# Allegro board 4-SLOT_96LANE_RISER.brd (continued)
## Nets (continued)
GND: C1.2(B) C2.2(B) C3.2(B) C4.2(B) C5.2(B) C6.2(B) C7.2(B) C8.2(B) C9.2(B) C10.2(B) C11.2(B) C12.2(B) C13.2(B) C14.2(B) C15.2(B) C16.2(B) C17.2(B) C18.2(B) C19.2(B) C20.2(B) C21.2(B) C22.2(B) C215.2(B) C216.2(B) C217.2(B) C218.2(B) C219.2(B) C220.2(B) C221.2(B) C222.2(B) C223.2(B) C224.2(B) C225.2(B) C226.2(B) C227.2(B) C228.2(B) C229.2(B) C230.2(B) C231.2(B) C232.2(B) C233.2(B) C234.2(B) C235.2(B) C236.2(B) C237.2(B) C238.2(B) C239.2(B) C240.2(B) C241.2(B) C242.2(B) C243.2(B) C244.2(B) C245.2(B) C246.2(B) C247.2(B) C248.2(B) C249.2(B) C250.2(B) C251.2(B) C252.2(B) C253.2(B) C254.2(B) C255.2(B) C256.2(B) C257.2(B) C258.2(B) C259.2(B) C261.2(B) C268.2(B) C269.2(B) C270.2(B) C271.2(B) C272.2(B) C273.2(B) C274.2(B) C275.2(B) C276.2(B) C277.2(B) C278.2(B) C279.2(B) C280.2(B) C281.2(B) C282.2(B) C283.2(B) C284.2(B) C285.2(B) C286.2(B) C287.2(B) C288.2(B) C289.2(B) C290.2(B) C291.2(B) C292.2(B) C293.2(B) C294.2(B) C295.2(B) C296.2(B) C297.2(B) C298.2(B) C299.2(B) C300.2(B) C301.2(B) C302.2(B) C303.2(B) C304.2(B) C305.2(B) C306.2(B) C307.2(B) C308.2(B) C309.2(B) C310.2(B) C311.2(B) C312.2(B) C313.2(B) C314.2(B) C315.2(B) C316.2(B) C317.2(B) C318.2(B) C319.2(B) C320.2(B) C321.2(B) C322.2(B) C323.2(B) C324.2(B) C325.2(B) C326.2(B) C327.2(B) C328.2(B) C329.2(B) C330.2(B) C331.2(B) C332.2(B) C333.2(B) C334.2(B) C335.2(B) C336.2(B) C337.2(B) C338.2(B) C339.2(B) C340.2(B) C341.2(B) C342.2(B) C343.2(B) C344.2(B) C345.2(B) C346.2(B) C347.2(B) C348.2(B) C349.2(B) C350.2(B) C351.2(B) C352.2(B) C353.2(B) C354.2(B) C355.2(B) C356.2(B) C357.2(B) C358.2(B) C359.2(B) C360.2(B) C361.2(B) C362.2(B) C363.2(B) C364.2(B) C365.2(B) C366.2(B) C367.2(B) C368.2(B) C369.2(B) C370.2(B) C371.2(B) C372.2(B) C373.2(B) C374.2(B) C375.2(B) C376.2(B) C377.2(B) C378.2(B) C379.2(B) C380.2(B) C381.2(B) C382.2(B) C383.2(B) C384.2(B) C385.2(B) C386.2(B) C387.2(B) C388.2(B) C389.2(B) C390.2(B) C391.2(B) C392.2(B) C393.2(B) C394.2(B) C395.2(B) C396.2(B) C397.2(B) C398.2(B) C399.2(B) C400.2(B) C401.2(B) C402.2(B) C403.2(B) C404.2(B) C405.2(B) C406.2(B) C407.2(B) C408.2(B) C409.2(B) C410.2(B) C411.2(B) C412.2(B) C413.2(B) C414.2(B) C415.2(B) C416.2(B) C417.2(B) C418.2(B) C419.2(B) C420.2(B) C421.2(B) C422.2(B) C423.2(B) C424.2(B) C425.2(B) C426.2(B) C427.2(B) C428.2(B) C429.2(B) C430.2(B) C431.2(B) C432.2(B) C433.2(B) C434.2(B) C435.2(B) C436.2(B) C437.2(B) C438.2(B) C439.2(B) C440.2(B) C441.2(B) C442.2(B) C443.2(B) C444.2(B) C445.2(B) C446.2(B) C447.2(B) C448.2(B) C449.2(B) C450.2(B) C451.2(B) C452.2(B) C453.2(B) C454.2(B) C455.2(B) C456.2(B) C457.2(B) C458.2(B) C459.2(B) C460.2(B) C461.2(B) C462.2(B) C463.2(B) C464.2(B) C465.2(B) C466.2(B) C467.2(B) C470.2(B) C471.2(B) C473.2(B) C474.2(B) C475.2(B) C476.2(B) C477.2(B) C478.2(B) C479.2(B) C480.2(B) CON1.4 J1.A4 J1.A12 J1.A15 J1.A18 J1.A20 J1.A23 J1.A24 J1.A27 J1.A28 J1.A31 J1.A34 J1.A37 J1.A38 J1.A41 J1.A42 J1.A45 J1.A46 J1.A49 J1.A51 J1.A54 J1.A55 J1.A58 J1.A59 J1.A62 J1.A63 J1.A66 J1.A67 J1.A70 J1.A71 J1.A74 J1.A75 J1.A78 J1.A79 J1.A82 J1.B4 J1.B7 J1.B13 J1.B16 J1.B18 J1.B21 J1.B22 J1.B25 J1.B26 J1.B29 J1.B32 J1.B35 J1.B36 J1.B39 J1.B40 J1.B43 J1.B44 J1.B47 J1.B49 J1.B52 J1.B53 J1.B56 J1.B57 J1.B60 J1.B61 J1.B64 J1.B65 J1.B68 J1.B69 J1.B72 J1.B73 J1.B76 J1.B77 J1.B80 J2.A4 J2.A12 J2.A15 J2.A18 J2.A20 J2.A23 J2.A24 J2.A27 J2.A28 J2.A31 J2.A34 J2.A37 J2.A38 J2.A41 J2.A42 J2.A45 J2.A46 J2.A49 J2.A51 J2.A54 J2.A55 J2.A58 J2.A59 J2.A62 J2.A63 J2.A66 J2.A67 J2.A70 J2.A71 J2.A74 J2.A75 J2.A78 J2.A79 J2.A82 J2.B4 J2.B7 J2.B13 J2.B16 J2.B18 J2.B21 J2.B22 J2.B25 J2.B26 J2.B29 J2.B32 J2.B35 J2.B36 J2.B39 J2.B40 J2.B43 J2.B44 J2.B47 J2.B49 J2.B52 J2.B53 J2.B56 J2.B57 J2.B60 J2.B61 J2.B64 J2.B65 J2.B68 J2.B69 J2.B72 J2.B73 J2.B76 J2.B77 J2.B80 J3.A4 J3.A12 J3.A15 J3.A18 J3.A20 J3.A23 J3.A24 J3.A27 J3.A28 J3.A31 J3.A34 J3.A37 J3.A38 J3.A41 J3.A42 J3.A45 J3.A46 J3.A49 J3.A51 J3.A54 J3.A55 J3.A58 J3.A59 J3.A62 J3.A63 J3.A66 J3.A67 J3.A70 J3.A71 J3.A74 J3.A75 J3.A78 J3.A79 J3.A82 J3.B4 J3.B7 J3.B13 J3.B16 J3.B18 J3.B21 J3.B22 J3.B25 J3.B26 J3.B29 J3.B32 J3.B35 J3.B36 J3.B39 J3.B40 J3.B43 J3.B44 J3.B47 J3.B49 J3.B52 J3.B53 J3.B56 J3.B57 J3.B60 J3.B61 J3.B64 J3.B65 J3.B68 J3.B69 J3.B72 J3.B73 J3.B76 J3.B77 J3.B80 J4.A4 J4.A12 J4.A15 J4.A18 J4.A20 J4.A23 J4.A24 J4.A27 J4.A28 J4.A31 J4.A34 J4.A37 J4.A38 J4.A41 J4.A42 J4.A45 J4.A46 J4.A49 J4.A51 J4.A54 J4.A55 J4.A58 J4.A59 J4.A62 J4.A63 J4.A66 J4.A67 J4.A70 J4.A71 J4.A74 J4.A75 J4.A78 J4.A79 J4.A82 J4.B4 J4.B7 J4.B13 J4.B16 J4.B18 J4.B21 J4.B22 J4.B25 J4.B26 J4.B29 J4.B32 J4.B35 J4.B36 J4.B39 J4.B40 J4.B43 J4.B44 J4.B47 J4.B49 J4.B52 J4.B53 J4.B56 J4.B57 J4.B60 J4.B61 J4.B64 J4.B65 J4.B68 J4.B69 J4.B72 J4.B73 J4.B76 J4.B77 J4.B80 J5.A4 J5.A12 J5.A15 J5.A18 J5.A20 J5.A23 J5.A24 J5.A27 J5.A28 J5.A31 J5.A34 J5.A37 J5.A38 J5.A41 J5.A42 J5.A45 J5.A46 J5.A49 J5.A51 J5.A54 J5.A55 J5.A58 J5.A59 J5.A62 J5.A63 J5.A66 J5.A67 J5.A70 J5.A71 J5.A74 J5.A75 J5.A78 J5.A79 J5.A82 J5.B4 J5.B7 J5.B13 J5.B16 J5.B18 J5.B21 J5.B22 J5.B25 J5.B26 J5.B29 J5.B32 J5.B35 J5.B36 J5.B39 J5.B40 J5.B43 J5.B44 J5.B47 J5.B49 J5.B52 J5.B53 J5.B56 J5.B57 J5.B60 J5.B61 J5.B64 J5.B65 J5.B68 J5.B69 J5.B72 J5.B73 J5.B76 J5.B77 J5.B80 J6.7 J6.8 J6.9 J6.10 J6.11 J6.12 J7.1 J7.4 J7.7 J7.10 J7.13 J7.16 J7.19 J7.22 J7.25 J7.26 J7.29 J7.32 J7.35 J7.38 J7.41 J7.44 J7.47 J7.50 J7.G1 J7.G2 J7.G3 J7.G4 J8.1 J8.4 J8.7 J8.10 J8.13 J8.16 J8.19 J8.22 J8.25 J8.28 J8.31 J8.34 J8.37 J8.38 J8.41 J8.44 J8.47 J8.50 J8.53 J8.56 J8.59 J8.62 J8.65 J8.68 J8.71 J8.74 J8.G1 J8.G2 J8.G3 J8.G4 MH1.1 MH2.2 MH2.3 MH2.4 MH2.5 MH2.6 MH3.2 MH3.3 MH3.4 MH3.5 MH3.6 MH4.2 MH4.3 MH4.4 MH4.5 MH4.6 MH5.2 MH5.3 MH5.4 MH5.5 MH5.6 MH6.2 MH6.3 MH6.4 MH6.5 MH6.6 MH7.2 MH7.3 MH7.4 MH7.5 MH7.6 MH8.1 PC453.2(B) PC454.2(B) PC455.2(B) PC456.2(B) PC457.2(B) PC458.2(B) PC459.2(B) PC460.2(B) PC461.2(B) PC462.2(B) PC463.2(B) PC464.2(B) PC465.2(B) PC466.2(B) PC467.2(B) PC468.2(B) PC471.2(B) PC472.2(B) PC475.2(B) PC476.2(B) PC477.2(B) PC478.2(B) PC479.2(B) PC480.2(B) PC481.2(B) PC482.2(B) PC483.2(B) PC484.2(B) PC485.2(B) PC486.2(B) PC487.2(B) PC488.2(B) PC489.2(B) PC491.2(B) PC492.2(B) PC493.2(B) PC495.2(B) PC498.2(B) PC500.2(B) PC501.2(B) PC502.2(B) PC503.2(B) PC505.2(B) PC506.2(B) PC508.1 PC510.2(B) PC511.2(B) PC515.2(B) PC517.2(B) PC519.2(B) PC520.2(B) PC521.2(B) PC522.2(B) PC523.2(B) PC524.2(B) PC526.2(B) PC529.2(B) PC530.2(B) PC531.2(B) PC532.2(B) PC533.2(B) PC534.2(B) PC535.2(B) PC537.2(B) PC538.2(B) PC539.2(B) PC541.2(B) PC542.2(B) PC543.2(B) PC545.2(B) PC548.2(B) PC550.2(B) PC551.2(B) PC552.2(B) PC553.2(B) PC554.2(B) PC556.2(B) PC557.2(B) PC558.2(B) PC559.2(B) PC563.2(B) PC564.2(B) PC565.2(B) PC566.2(B) PC567.2(B) PC568.2(B) PC569.2(B) PC570.2(B) PC571.2(B) PC572.2(B) PC573.2(B) PC574.2(B) PC575.2(B) PC576.2(B) PC577.2(B) PC578.2(B) PC579.2(B) PC580.2(B) PC581.1 PC583.2(B) PC584.2(B) PC585.2(B) PC586.2(B) PC588.2(B) PC592.2(B) PC593.2(B) PC594.2(B) PC595.2(B) PC596.2(B) PC598.2(B) PC599.2(B) PC600.2(B) PC612.2(B) PC613.2(B) PC614.2(B) PC615.2(B) PC620.2(B) PC621.2(B) PC623.2(B) PC660.2(B) PC661.2(B) PC1523.2(B) PC1531.2(B) PC1533.2(B) PC1585.2(B) PC1586.2(B) PC1588.2(B) PC1589.2(B) PC1592.2(B) PC1594.2(B) PC1595.2(B) PC1596.2(B) PC1598.2(B) PC1599.2(B) PC1600.2(B) PC1621.2(B) PC1623.2(B) PC2531.2(B) PC2533.2(B) PC2596.2(B) PQ6.1 PQ6.4 PQ7.1 PQ7.4 PR295.2(B) PR297.2(B) PR302.2(B) PR303.2(B) PR315.2(B) PR323.2(B) PR333.2(B) PR340.2(B) PR356.2(B) PR361.2(B) PR369.2(B) PR376.1 PR397.2(B) PR399.2(B) PR401.2(B) PR403.2(B) PR406.2(B) PR408.2(B) PR409.2(B) PR414.2(B) PR424.2(B) PR435.2(B) PR503.1 PR505.2(B) PU13.5 PU13.16 PU13.17 PU13.18 PU13.19 PU13.20 PU13.21 PU13.22 PU13.23 PU13.24 PU13.25 PU13.26 PU13.27 PU13.28 PU13.37 PU13.41 PU15.5 PU15.16 PU15.17 PU15.18 PU15.19 PU15.20 PU15.21 PU15.22 PU15.23 PU15.24 PU15.25 PU15.26 PU15.27 PU15.28 PU15.37 PU15.41 PU16.10 PU17.11 PU18.3 PU18.7 PU19.10 PU20.2 PU20.3 PU20.EP PU21.29 PU22.2 PU22.3 PU22.EP PU23.11 Q1.S Q2.S Q3.S Q4.S Q7.S R2.2(B) R9.2(B) R10.1 R11.1 R12.1 R13.1 R14.1 R15.1 R16.1 R17.1 R18.1 R31.1 R32.1 R33.1 R34.1 R35.1 R36.1 R37.1 R38.1 R39.1 R40.1 R41.1 R42.1 R43.1 R44.1 R45.1 R46.1 R47.1 R48.1 R49.1 R50.1 R51.1 R52.1 R53.1 R54.1 R55.1 R56.1 R57.1 R58.1 R59.1 R60.1 R61.1 R62.1 R63.1 R64.1 R65.1 R66.1 R67.1 R68.1 R69.1 R70.1 R71.1 R72.1 R73.1 R74.1 R75.1 R76.1 R80.2(B) R82.2(B) R84.2(B) R111.1 R112.1 R129.2(B) R131.2(B) R133.2(B) R135.2(B) R140.2(B) R164.1 R165.1 R166.1 R167.1 R168.1 R169.1 R170.1 R171.1 R173.2(B) R174.2(B) R175.2(B) R176.2(B) R178.2(B) R180.2(B) R182.2(B) R197.1 R198.1 R199.1 R200.1 R205.1 R206.1 R207.1 R208.1 R217.1 R218.1 R219.1 R220.1 R229.1 R230.1 R231.1 R232.1 R241.1 R242.1 R243.1 R244.1 R246.1 R251.1 R253.1 R254.1 R255.1 R256.1 R260.1 R265.1 R266.1 R267.1 R268.1 R275.1 R282.2(B) R284.2(B) R286.2(B) R288.2(B) R290.2(B) R292.2(B) R294.2(B) R318.2(B) R319.2(B) R320.2(B) R321.2(B) R322.2(B) R323.2(B) R324.1 R325.1 R327.2(B) R329.2(B) R331.2(B) R343.1 R344.1 R345.1 R346.2(B) U1.A1 U1.A4 U1.A29 U1.A34 U1.AA3 U1.AA7 U1.AA12 U1.AA14 U1.AA16 U1.AA18 U1.AA22 U1.AA24 U1.AA26 U1.AA28 U1.AA32 U1.AB3 U1.AB6 U1.AB9 U1.AB11 U1.AB13 U1.AB17 U1.AB19 U1.AB21 U1.AB23 U1.AB32 U1.AC3 U1.AC26 U1.AC29 U1.AC32 U1.AD3 U1.AD9 U1.AD11 U1.AD13 U1.AD17 U1.AD22 U1.AD24 U1.AD32 U1.AE3 U1.AE10 U1.AE14 U1.AE16 U1.AE18 U1.AE22 U1.AE25 U1.AE32 U1.AF3 U1.AF7 U1.AF28 U1.AF32 U1.AG3 U1.AG7 U1.AG32 U1.AH3 U1.AH10 U1.AH12 U1.AH16 U1.AH20 U1.AH25 U1.AH28 U1.AH29 U1.AH32 U1.AJ3 U1.AJ6 U1.AJ7 U1.AJ12 U1.AJ13 U1.AJ15 U1.AJ19 U1.AJ22 U1.AJ25 U1.AJ28 U1.AJ29 U1.AJ32 U1.AK3 U1.AK6 U1.AK31 U1.AK32 U1.AK33 U1.AK34 U1.AL1 U1.AL2 U1.AL3 U1.AL4 U1.AL5 U1.AL6 U1.AL31 U1.AM3 U1.AM6 U1.AM7 U1.AM8 U1.AM9 U1.AM10(VSS<9>) U1.AM11 U1.AM12 U1.AM13 U1.AM14 U1.AM15 U1.AM16 U1.AM17 U1.AM18 U1.AM19 U1.AM20 U1.AM21 U1.AM22 U1.AM23 U1.AM24 U1.AM25 U1.AM26 U1.AM27 U1.AM28 U1.AM29 U1.AM30 U1.AM31 U1.AN1 U1.AN2 U1.AN6 U1.AN31 U1.AP1 U1.AP6 U1.AP31 U1.AP34 U1.B4 U1.B29 U1.C4 U1.C5 U1.C6 U1.C7 U1.C8 U1.C9 U1.C10 U1.C11 U1.C12 U1.C13 U1.C14 U1.C15 U1.C16 U1.C17 U1.C18 U1.C19 U1.C20 U1.C21 U1.C22 U1.C23 U1.C24 U1.C25 U1.C26 U1.C27 U1.C28 U1.C29 U1.D4 U1.D29 U1.D30 U1.D31 U1.D32 U1.D33 U1.D34 U1.E1 U1.E2 U1.E3 U1.E4 U1.E29 U1.E32 U1.F3 U1.F6 U1.F7 U1.F12 U1.F15 U1.F20 U1.F21 U1.F22 U1.F23 U1.F28 U1.F29 U1.F32 U1.G3 U1.G6 U1.G12 U1.G17 U1.G32 U1.H3 U1.H27 U1.H28 U1.H32 U1.J3 U1.J32 U1.K3 U1.K7 U1.K10 U1.K15 U1.K19 U1.K22 U1.K25 U1.K28 U1.K32 U1.L3 U1.L9 U1.L11 U1.L13 U1.L17 U1.L22 U1.L24 U1.L26 U1.L32 U1.M3 U1.M32 U1.N3 U1.N6 U1.N12 U1.N14 U1.N16 U1.N18 U1.N22 U1.N24 U1.N26 U1.N29 U1.N32 U1.P3 U1.P9 U1.P11 U1.P13 U1.P17 U1.P19 U1.P21 U1.P23 U1.P28 U1.P32 U1.R3 U1.R10 U1.R12 U1.R14 U1.R16 U1.R18 U1.R22 U1.R24 U1.R26 U1.R32 U1.T3 U1.T9 U1.T11 U1.T13 U1.T15 U1.T17 U1.T19 U1.T21 U1.T23 U1.T25 U1.T32 U1.U3 U1.U6 U1.U10 U1.U12 U1.U14 U1.U16 U1.U18 U1.U20 U1.U22 U1.U24 U1.U26 U1.U32 U1.V3 U1.V9 U1.V11 U1.V13 U1.V15 U1.V17 U1.V19 U1.V21 U1.V23 U1.V25 U1.V28 U1.V29 U1.V32 U1.W3 U1.W10 U1.W12 U1.W14 U1.W16 U1.W18 U1.W20 U1.W22 U1.W24 U1.W26 U1.W32 U1.Y3 U1.Y9 U1.Y11 U1.Y13 U1.Y17 U1.Y19 U1.Y21 U1.Y23 U1.Y25 U1.Y32 U2.12 U3.4 U3.41 U4.5 U6.4 U7.4 U10.6 U12.4 U13.3 U15.3 U16.3 U17.3 U18.3 U19.3 U20.3 U21.3 U22.3
GND_L: U5.3 U5.4 U5.5 U5.6 U5.7 U5.8 U5.9 U5.10 U5.11 U5.12 U23.3 U23.4 U23.5 U23.6 U23.7 U23.8 U23.9 U23.10 U23.11 U23.12 U25.3 U25.4 U25.5 U25.6 U25.7 U25.8 U25.9 U25.10 U25.11 U25.12 U26.3 U26.4 U26.5 U26.6 U26.7 U26.8 U26.9 U26.10 U26.11 U26.12 U27.3 U27.4 U27.5 U27.6 U27.7 U27.8 U27.9 U27.10 U27.11 U27.12 U29.3 U29.4 U29.5 U29.6 U29.7 U29.8 U29.9 U29.10 U29.11 U29.12 U30.3 U30.4 U30.5 U30.6 U30.7 U30.8 U30.9 U30.10 U30.11 U30.12 U31.3 U31.4 U31.5 U31.6 U31.7 U31.8 U31.9 U31.10 U31.11 U31.12 U33.3 U33.4 U33.5 U33.6 U33.7 U33.8 U33.9 U33.10 U33.11 U33.12 U34.3 U34.4 U34.5 U34.6 U34.7 U34.8 U34.9 U34.10 U34.11 U34.12 U35.3 U35.4 U35.5 U35.6 U35.7 U35.8 U35.9 U35.10 U35.11 U35.12 U37.3 U37.4 U37.5 U37.6 U37.7 U37.8 U37.9 U37.10 U37.11 U37.12 U39.3 U39.4 U39.5 U39.6 U39.7 U39.8 U39.9 U39.10 U39.11 U39.12 U41.3 U41.4 U41.5 U41.6 U41.7 U41.8 U41.9 U41.10 U41.11 U41.12 U43.3 U43.4 U43.5 U43.6 U43.7 U43.8 U43.9 U43.10 U43.11 U43.12 U45.3 U45.4 U45.5 U45.6 U45.7 U45.8 U45.9 U45.10 U45.11 U45.12
P0V9: C1.1 C2.1 C3.1 C4.1 C5.1 C6.1 C7.1 C8.1 C9.1 C10.1 C16.1 C17.1 C18.1 C19.1 C20.1 C21.1 C22.1 C268.1 C269.1 C270.1 C271.1 C272.1 C273.1 C274.1 C275.1 C276.1 C277.1 C278.1 C279.1 C280.1 C281.1 C282.1 C283.1 C285.1 C287.1 C289.1 C290.1 C292.1 C294.1 C296.1 C297.1 C299.1 C300.1 C301.1 C378.1 C380.1 C382.1 C384.1 C386.1 C388.1 C390.1 C392.1 C394.1 C396.1 C398.1 C400.1 C402.1 C404.1 C406.1 C408.1 C410.1 C412.1 C414.1 C416.1 C418.1 C420.1 C422.1 C424.1 C426.1 C428.1 C430.1 C432.1 C434.1 C436.1 C438.1 C440.1 C442.1 C444.1 C446.1 C448.1 PC475.1 PC476.1 PC477.1 PC478.1 PC479.1 PC480.1 PC481.1 PC482.1 PC483.1 PC484.1 PC485.1 PC486.1 PC487.1 PC488.1 PC660.1 PC661.1 PL2.2A PL3.2A PR377.1 PR378.1 U1.AA11 U1.AA13 U1.AA17 U1.AA19 U1.AA21 U1.AA23 U1.AB12 U1.AB14 U1.AB16 U1.AB18 U1.AB22 U1.AB24 U1.N11 U1.N13 U1.N17 U1.N19 U1.N21 U1.N23 U1.P12 U1.P14 U1.P16 U1.P18 U1.P22 U1.P24 U1.R11 U1.R13 U1.R17 U1.R19 U1.R21 U1.R23 U1.T10 U1.T12 U1.T14 U1.T16 U1.T18 U1.T20 U1.T22 U1.T24 U1.U11 U1.U13 U1.U15 U1.U17 U1.U19 U1.U21 U1.U23 U1.U25 U1.V10 U1.V12 U1.V14 U1.V16 U1.V18 U1.V20 U1.V22 U1.V24 U1.W11 U1.W13 U1.W15 U1.W17 U1.W19 U1.W21 U1.W23 U1.W25 U1.Y12 U1.Y14 U1.Y16 U1.Y18 U1.Y22 U1.Y24
P0V9_A: C324.1 C325.1 C326.1 C327.1 C328.1 C329.1 C330.1 C331.1 C332.1 C333.1 C334.1 C335.1 C336.1 C337.1 C338.1 C339.1 C340.1 C341.1 C342.1 C343.1 C344.1 C345.1 C346.1 C347.1 C348.1 C349.1 C350.1 C351.1 C352.1 C353.1 C354.1 C355.1 C356.1 C357.1 C358.1 C359.1 C360.1 C361.1 C362.1 C363.1 C364.1 C365.1 C366.1 C367.1 C379.1 C381.1 C383.1 C385.1 C387.1 C389.1 C391.1 C393.1 C395.1 C397.1 C399.1 C401.1 C403.1 C405.1 C407.1 C409.1 C411.1 C413.1 C415.1 C417.1 C419.1 C421.1 C423.1 C425.1 C427.1 C429.1 C431.1 C433.1 C435.1 C437.1 C439.1 C441.1 C443.1 C445.1 C447.1 C449.1 PR433.2(B) PR434.2(B) SHORT6.2 SHORT7.2 SHORT8.2 SHORT9.2 SHORT10.2 U1.AA10 U1.AA15 U1.AA20 U1.AA25 U1.AB10 U1.AB15 U1.AB20 U1.AB25 U1.AC10 U1.AC11 U1.AC12 U1.AC13 U1.AC14 U1.AC15 U1.AC16 U1.AC17 U1.AC18 U1.AC19 U1.AC20 U1.AC21 U1.AC22 U1.AC23 U1.AC24 U1.AC25 U1.AD10 U1.AD14 U1.AD16 U1.AD19 U1.AD21 U1.AD25 U1.L10 U1.L14 U1.L16 U1.L19 U1.L21 U1.L25 U1.M10 U1.M11 U1.M12 U1.M13 U1.M14 U1.M15 U1.M16 U1.M17 U1.M18 U1.M19 U1.M20 U1.M21 U1.M22 U1.M23 U1.M24 U1.M25 U1.N10 U1.N15 U1.N20 U1.N25 U1.P10 U1.P15 U1.P20 U1.P25 U1.R15 U1.R20 U1.R25 U1.Y10 U1.Y15 U1.Y20
P0V9_AGND: PR389.2(B) PR393.2(B) PR394.1 PR395.1 PR396.1 PR397.1 PU21.3
P0V9_CNFG: PR394.2(B) PU21.12
P0V9_COMP1: PC561.2(B) PC562.2(B) PU21.24
P0V9_COMP1_RC: PC562.1 PR387.2(B)
P0V9_DLY1: PR393.1 PU21.8
P0V9_DRVON: PC573.1 PQ6.3 PQ7.6 PR401.1 PR404.1 PU21.4
P0V9_EN1: PC566.1 PR391.2(B) PR392.2(B) PU21.2
P0V9_FB1: PC560.2(B) PC561.1 PR383.2(B) PR385.1 PR387.1 PU21.23
P0V9_FB1_RC: PC560.1 PR382.2(B)
P0V9_FSET: PR396.2(B) PU21.11
P0V9_ILIMT1: PC576.1 PR408.1 PR410.1 PU21.26
P0V9_IS1_N: PC473.2(B) PC700.1 PR310.2(B) PU21.20
P0V9_IS1_P: PC473.1 PR308.2(B) PR800.2(B)
P0V9_IS2_N: PC474.2(B) PC701.2(B) PR311.2(B) PU21.18
P0V9_IS2_P: PC474.1 PR309.2(B) PR801.2(B)
P0V9_OTP1: PR409.1 PR411.1 PU21.25
P0V9_PG1: PC564.1 PR390.2(B) PU21.5 R297.1 U22.2
P0V9_PG_LED: Q7.G U22.4(Y)
P0V9_PG_LED_H: D1.A R110.1
P0V9_PG_LED_N: D1.C Q7.D R109.2(B)
P0V9_PWM1: PR296.2(B) PR297.1 PU15.40 PU21.22
P0V9_PWM2: PR143.2(B) PR295.1 PU13.40 PU21.17
P0V9_SENSE1_N: PR376.2(B) PR385.2(B) PR389.1 PR503.2(B)
P0V9_SENSE1_P: PR377.2(B) PR378.2(B) PR382.1 PR383.1
P0V9_SS: PR395.2(B) PU21.10
P0V9_VCC5V: PC568.1 PR404.2(B) PU21.28
P0V9_VCIN1: PC468.1 PR301.2(B) PU15.2 PU15.39
P0V9_VCIN2: PC467.1 PR300.2(B) PU13.2 PU13.39
P0V9_VIN: PC572.1 PR400.1 PU21.1
P0V9_VREF: PC567.1 PR410.2(B) PR411.2(B) PU21.27(VREF)
P0V9_ZCD_EN1_N: PR298.2(B) PR303.1 PU15.1(ZCD_EN#)
P0V9_ZCD_EN2_N: PR299.2(B) PR302.1 PU13.1(ZCD_EN#)
P0V9A_AGND: PC582.2(B) PR423.2(B) PR424.1 PR504.1 PU23.4 PU23.17
P0V9A_COMP: PC589.1 PR427.1 PU23.3
P0V9A_COMP_RC: PC591.1 PR427.2(B)
P0V9A_EN: PC580.1 PR418.2(B) PU23.15
P0V9A_FB: PC589.2(B) PC591.2(B) PR429.2(B) PR431.1 PR432.1 PU23.1
P0V9A_FB_RC: PC597.1 PR431.2(B)
P0V9A_OUT: PC592.1 PC594.1 PC595.1 PC596.1 PC598.1 PC599.1 PC600.1 PC1592.1 PC1594.1 PC1595.1 PC1596.1 PC1598.1 PC1599.1 PC1600.1 PC2596.1 PL11.2 PR430.2(B) SHORT6.1 SHORT7.1 SHORT8.1 SHORT9.1 SHORT10.1
P0V9A_PG: PR420.2(B) PU23.7 U22.1
P0V9A_RT: PR423.1 PU23.5
P0V9A_SENSE_R_N: PR428.1 PR429.1 PR435.1 PR504.2(B) PR505.1
P0V9A_SENSE_R_P: PC597.2(B) PR432.2(B) PR433.1 PR434.1
P0V9A_VCC: PC581.2(B) PU23.6 PU23.10
P0V9A_VIN: PC583.1 PR426.2(B) PU23.9
P0V9A_VREF: PC582.1 PU23.2
P0V9A_VSNS: PR428.2(B) PR430.1 PU23.8(VSNS)
P1V8: C11.1 C12.1 C13.1 C14.1 C15.1 C256.1 C284.1 C286.1 C288.1 C291.1 C293.1 C295.1 C298.1 C368.1 C369.1 C370.1 C371.1 C372.1 C373.1 C374.1 C375.1 C376.1 C377.1 C451.1 R128.1 R130.1 R132.1 R134.1 R136.1 R137.1 R138.1 R139.1 R141.1 R142.1 R143.1 R146.1 R147.1 R148.1 R149.1 R150.1 R151.1 R172.1 R177.1 R179.1 R181.1 R187.1 R188.1 R189.1 R190.1 R201.1 R202.1 R272.1 R273.1 R274.1 R277.1 R278.1 R287.1 R289.1 R291.1 R295.1 R326.1 R328.1 R330.1 R332.1 R333.1 R334.1 R335.1 R351.1 SHORT105.2 U1.AG8 U1.AG15 U1.AG22 U1.AG28 U1.J9 U1.J15 U1.J21 U1.J26 U1.R9 U1.T26 U1.U9 U1.V26 U1.W9 U1.Y26 U6.8 U12.1
P1V8_A: C302.1 C303.1 C304.1 C305.1 C306.1 C307.1 C308.1 C309.1 C310.1 C311.1 C312.1 C313.1 C314.1 C315.1 C316.1 C317.1 C318.1 C319.1 C320.1 C321.1 C322.1 C323.1 C457.1 C458.1 SHORT5.2 U1.AA9 U1.AB26 U1.AD12 U1.AD15 U1.AD18 U1.AD20 U1.AD23 U1.AN32 U1.B30 U1.L12 U1.L15 U1.L18 U1.L20 U1.L23 U1.N9 U1.P26
P1V8_EN: PR353.2(B) PU18.4
P1V8_FB: PC536.2(B) PR355.2(B) PR356.1 PU18.2
P1V8A_AGND: PR367.2(B) PR368.2(B) PR369.1 PR372.1 PU19.4 PU19.9 PU19.13 PU19.16
P1V8A_COMP: PC547.1 PR371.1 PU19.3
P1V8A_COMP_RC: PC549.1 PR371.2(B)
P1V8A_EN: PC539.1 PR357.2(B) PR361.1 PU19.15
P1V8A_FB: PC547.2(B) PC549.2(B) PR372.2(B) PR373.1 PR374.1 PU19.1
P1V8A_FB_RC: PC555.1 PR373.2(B)
P1V8A_OUT: PC551.1 PC552.1 PC554.1 PC556.1 PC557.1 PL8.2 PR375.2(B) SHORT5.1
P1V8A_PG: PR363.2(B) PR392.1 PR418.1 PU19.6 R211.2(B)
P1V8A_RT: PR368.1 PU19.5
P1V8A_SS: PR366.2(B) PR367.1 PU19.2
P1V8A_VCC: PC541.1 PR366.1 PU19.8
P1V8A_VIN: PC542.1 PR370.2(B) PU19.7
P1V8A_VSENSE_R: PC555.2(B) PR374.2(B) PR375.1
P3V3: C231.1 C232.1 C233.1 C238.1 C239.1 C240.1 C245.1 C246.1 C247.1 C252.1 C253.1 C254.1 C450.1 C453.1 C454.1 C455.1 C456.1 C470.1 C474.1 C476.1 C478.1 C480.1 CON1.1 J1.A9 J1.A10 J1.B8 J2.A9 J2.A10 J2.B8 J3.A9 J3.A10 J3.B8 J4.A9 J4.A10 J4.B8 L1.2 PC534.1 PC535.1 PR336.1 PR363.1 PR390.1 PR420.1 PU18.6 R3.1 R4.1 R77.1 R93.1 R94.1 R107.1 R108.1 R109.1 R110.2(B) R152.1 R153.1 R154.1 R155.1 R156.1 R157.1 R158.1 R159.1 R160.1 R161.1 R162.1 R163.1 R191.1 R192.1 R193.1 R194.1 R203.1 R204.1 R209.1 R210.1 R296.1 R305.1 R306.1 R307.1 R308.1 R348.1 R349.1 R350.1 R352.1 R353.1 SHORT1.2 SHORT2.2 SHORT3.2 SHORT4.2 SHORT11.2 SHORT12.2 U12.8(VCCB) U13.5 U15.5 U16.5 U17.5 U22.5
P3V3_AGND: PC509.2(B) PR339.2(B) PR340.1 PR343.1 PR344.1 PU17.4 PU17.17
P3V3_BUF_VDDA: C224.1 C225.1 R92.2(B) U3.1
P3V3_BUF_VDDR: C226.1 C227.1 R91.2(B) U3.5
P3V3_CLK_BUF_VDD: C215.1 C216.1 C217.1 C218.1 C219.1 C220.1 C221.1 C222.1 C257.1 C258.1 L1.1 R1.1 R91.1 R92.1 U3.12 U3.16 U3.20 U3.21 U3.25 U3.29 U3.31 U3.35 U3.39
P3V3_COMP: PC516.1 PR342.1 PU17.3
P3V3_COMP_RC: PC518.1 PR342.2(B)
P3V3_EN: PC506.1 PR332.2(B) PR333.1 PU17.15
P3V3_FB: PC516.2(B) PC518.2(B) PR344.2(B) PR346.1 PR347.1 PU17.1
P3V3_FB_RC: PC527.1 PR346.2(B)
P3V3_MB: J5.A9 J5.A10 J5.B8
P3V3_OUT: PC522.1 PC524.1 PC526.1 PC529.1 PC530.1 PC531.1 PC533.1 PC612.1 PC613.1 PC614.1 PC615.1 PC1531.1 PC1533.1 PC2531.1 PC2533.1 PL6.2 PR345.2(B) PR348.2(B) SHORT1.1 SHORT2.1 SHORT3.1 SHORT4.1 SHORT11.1 SHORT12.1
P3V3_PG: PR336.2(B) PR353.1 PR357.1 PR391.1 PU17.7 R298.1
P3V3_RT: PR339.1 PU17.5
P3V3_SENSE_R: PC527.2(B) PR347.2(B) PR348.1
P3V3_STBY: C234.1 C241.1 C248.1 C255.1 J1.B10 J2.B10 J3.B10 J4.B10 PR317.1 PR330.2(B) R238.1 R239.1 R240.1 R245.1 R247.1 R248.1 R249.1 R250.1 R252.1 R257.1 R258.1 R259.1 R261.1 R262.1 R263.1 R264.1
P3V3_STBY_AGND: PR321.2(B) PR322.2(B) PR323.1 PR326.1 PU16.4 PU16.9 PU16.13 PU16.16
P3V3_STBY_COMP: PC497.1 PR325.1 PU16.3
P3V3_STBY_COMP_RC: PC499.1 PR325.2(B)
P3V3_STBY_EN: PC489.1 PR314.2(B) PR315.1 PU16.15
P3V3_STBY_FB: PC497.2(B) PC499.2(B) PR326.2(B) PR327.1 PR328.1 PU16.1
P3V3_STBY_FB_RC: PC504.1 PR327.2(B)
P3V3_STBY_MB: C223.1 C259.1 C261.1 C452.1 C459.1 C460.1 C461.1 C462.1 J5.B10 R78.1 R79.1 R81.1 R83.1 R87.1 R88.1 R95.1 R96.1 R97.1 R98.1 R99.1 R100.1 R101.1 R102.1 R103.1 R104.1 R105.1 R106.1 R144.1 R145.1 R185.1 R186.1 R281.1 R283.1 R285.1 R293.1 R301.1 R302.1 R303.1 R304.1 R309.1 U2.24 U4.1(VDD) U7.8 U10.1(VDD) U18.5 U19.5 U20.5 U21.5
P3V3_STBY_OUT: C471.1 PC500.1 PC501.1 PC503.1 PC505.1 PC623.1 PC1623.1 PL4.2 PR329.2(B) PR330.1
P3V3_STBY_PG: PR317.2(B) PU16.6
P3V3_STBY_RT: PR322.1 PU16.5
P3V3_STBY_SS: PR320.2(B) PR321.1 PU16.2
P3V3_STBY_VIN: PC492.1 PR324.2(B) PU16.7
P3V3_STBY_VSENSE_R: PC504.2(B) PR328.2(B) PR329.1
P3V3_VCC: PC508.2(B) PU17.6 PU17.10
P3V3_VIN: PC510.1 PR341.2(B) PU17.9
P3V3_VREF: PC509.1 PU17.2
P3V3_VSNS: PR343.2(B) PR345.1 PU17.8(VSNS)
P5V_STBY_VCC: PC491.1 PR320.1 PU16.8
P12V: C228.1 C229.1 C230.1 C235.1 C236.1 C237.1 C242.1 C243.1 C244.1 C249.1 C250.1 C251.1 C463.1 C464.1 C465.1 C473.1 C475.1 C477.1 C479.1 J1.A2 J1.A3 J1.B1 J1.B2 J1.B3 J2.A2 J2.A3 J2.B1 J2.B2 J2.B3 J3.A2 J3.A3 J3.B1 J3.B2 J3.B3 J4.A2 J4.A3 J4.B1 J4.B2 J4.B3 J6.1 J6.2 J6.3 J6.4 J6.5 PC532.1 PC553.1 PC558.1 PC563.1 PC565.1 PC574.1 PC575.1 PC593.1 PL7.2 PL9.2 PL10.1 PL12.2 PL20.2 PL510.1 PR332.1 PR402.1 PR405.1 PU20.1 PU22.1
P12V_MB: J5.A2 J5.A3 J5.B1 J5.B2 J5.B3
P12V_PSU: C466.1 C467.1 J6.6 PC502.1 PL5.2 PR314.1
VCC_P5V_1: PC569.1 PC571.1 PR296.1 PR298.1 PR301.1 PR398.1 PR407.1 PU20.6(VOUT)
VCC_P5V_2: PC577.1 PC579.1 PR143.1 PR299.1 PR300.1 PR407.2(B) PR413.1 PU22.6(VOUT)
2N7002_G1_D2: PQ7.2 PQ7.3 PR405.2(B) PR406.1
2N7002_G2_R: PC578.1 PQ7.5 PR413.2(B) PR414.1
85OHM_BOT_5INCH_DN: U39.1 U41.2
85OHM_BOT_5INCH_DP: U39.2 U41.1
85OHM_BOT_10INCH_DN: U43.1 U45.2
85OHM_BOT_10INCH_DP: U43.2 U45.1
85OHM_L1_5INCH_DN: U23.1 U27.2
85OHM_L1_5INCH_DP: U23.2 U27.1
85OHM_L1_10INCH_DN: U31.1 U35.2
85OHM_L1_10INCH_DP: U31.2 U35.1
85OHM_L3_5INCH_DN: U25.1 U29.2
85OHM_L3_5INCH_DP: U25.2 U29.1
85OHM_L3_10INCH_DN: U33.1 U37.2
85OHM_L3_10INCH_DP: U33.2 U37.1
85OHM_TOP_5INCH_DN: U5.1 U26.2
85OHM_TOP_5INCH_DP: U5.2 U26.1
85OHM_TOP_10INCH_DN: U30.1 U34.2
85OHM_TOP_10INCH_DP: U30.2 U34.1
AT24C64_A0: R281.2(B) R282.1 U7.1
AT24C64_A1: R283.2(B) R284.1 U7.2
AT24C64_A2: R285.2(B) R286.1 U7.3
AT24C64_WP: R293.2(B) R294.1 U7.7(WP)
CLK_100M_CPU1_PE_FG_DN: J5.A14 U3.7
CLK_100M_CPU1_PE_FG_DP: J5.A13 U3.6
CLK_100M_PEX8796_DN: R127.1 U3.34
CLK_100M_PEX8796_DP: R126.1 U3.33
CLK_100M_PEX8796_R_DN: R127.2(B) U1.AM1
CLK_100M_PEX8796_R_DP: R126.2(B) U1.AM2
CLK_100M_SLOT1_DN: R125.1 U3.27
CLK_100M_SLOT1_DP: R124.1 U3.26
CLK_100M_SLOT1_R_DN: J1.A14 R125.2(B)
CLK_100M_SLOT1_R_DP: J1.A13 R124.2(B)
CLK_100M_SLOT2_DN: R123.1 U3.24
CLK_100M_SLOT2_DP: R122.1 U3.23
CLK_100M_SLOT2_R_DN: J2.A14 R123.2(B)
CLK_100M_SLOT2_R_DP: J2.A13 R122.2(B)
CLK_100M_SLOT3_DN: R121.1 U3.18
CLK_100M_SLOT3_DP: R120.1 U3.17
CLK_100M_SLOT3_R_DN: J3.A14 R121.2(B)
CLK_100M_SLOT3_R_DP: J3.A13 R120.2(B)
CLK_100M_SLOT4_DN: R119.1 U3.15
CLK_100M_SLOT4_DP: R118.1 U3.14
CLK_100M_SLOT4_R_DN: J4.A14 R119.2(B)
CLK_100M_SLOT4_R_DP: J4.A13 R118.2(B)
CLK_BUF_CKPWRGD: Q4.D R4.2(B) U3.3
CLK_BUF_HIBW_BYPM_LOBW_N: R1.2(B) R2.1 U3.2
CPLD_PWRBRK_N: J5.B30 R309.2(B) U18.2 U19.2 U20.2 U21.2
CPLD_SLOT1_PWRBRK_N: R216.1 R221.1 R306.2(B) U20.4(Y)
CPLD_SLOT1_PWRBRK_R1_N: J1.B12 R216.2(B)
CPLD_SLOT1_PWRBRK_R2_N: J1.B30 R221.2(B)
CPLD_SLOT2_PWRBRK_N: R214.1 R215.1 R308.2(B) U19.4(Y)
CPLD_SLOT2_PWRBRK_R1_N: J2.B12 R214.2(B)
CPLD_SLOT2_PWRBRK_R2_N: J2.B30 R215.2(B)
CPLD_SLOT3_PWRBRK_N: R212.1 R213.1 R305.2(B) U21.4(Y)
CPLD_SLOT3_PWRBRK_R1_N: J3.B12 R212.2(B)
CPLD_SLOT3_PWRBRK_R2_N: J3.B30 R213.2(B)
CPLD_SLOT4_PWRBRK_N: R195.1 R196.1 R307.2(B) U18.4(Y)
CPLD_SLOT4_PWRBRK_R1_N: J4.B12 R195.2(B)
CPLD_SLOT4_PWRBRK_R2_N: J4.B30 R196.2(B)
EMC1412_ADDR: R302.2(B) U4.4
EMC1412_ALERT: R301.2(B) U4.6
EMC1413_ADDR: R303.2(B) U10.7
EMC1413_ALERT_N: R304.2(B) U10.8
I2C_MUX_ADD_A0: R83.2(B) R84.1 U2.1
I2C_MUX_ADD_A1: R81.2(B) R82.1 U2.2
I2C_MUX_ADD_A2: R79.2(B) R80.1 U2.21
I2C_MUX_RST_N: R78.2(B) U2.3
I2C_PCA9548_2N7002_G2_SCL: Q19.G R160.2(B)
I2C_PCA9548_2N7002_G2_SDA: Q22.G R163.2(B)
I2C_PCA9548_2N7002_G_SCL: Q20.G R161.2(B)
I2C_PCA9548_2N7002_G_SDA: Q23.G R191.2(B)
I2C_PCA9548_SC0_SLOT4_R_SCL: R20.1 U2.5
I2C_PCA9548_SC0_SLOT4_SCL: Q13.D R20.2(B) R96.2(B) R224.1
I2C_PCA9548_SC1_SLOT3_R_SCL: R22.1 U2.7
I2C_PCA9548_SC1_SLOT3_SCL: Q14.D R22.2(B) R98.2(B) R222.1
I2C_PCA9548_SC2_SLOT2_R_SCL: R24.1 U2.9
I2C_PCA9548_SC2_SLOT2_SCL: Q15.D R24.2(B) R100.2(B) R226.1
I2C_PCA9548_SC3_SLOT1_R_SCL: R26.1 U2.11
I2C_PCA9548_SC3_SLOT1_SCL: Q21.D R26.2(B) R102.2(B) R228.1
I2C_PCA9548_SC5_3V3_PE_SCL: CON1.2 Q20.S R194.2(B) R234.2(B) U12.7
I2C_PCA9548_SC5_P1V8_SCL: R277.2(B) U1.R8 U12.2
I2C_PCA9548_SC5_PE_R_SCL: R28.1 U2.16
I2C_PCA9548_SC5_PE_SCL: Q20.D R28.2(B) R104.2(B) R234.1
I2C_PCA9548_SC6_3V3_CLK_R_SCL: R90.2(B) U3.9
I2C_PCA9548_SC6_3V3_CLK_SCL: Q19.S R90.1 R193.2(B) R236.2(B)
I2C_PCA9548_SC6_CLK_R_SCL: R30.1 U2.18
I2C_PCA9548_SC6_CLK_SCL: Q19.D R30.2(B) R106.2(B) R183.1 R236.1 R280.2(B) R299.1
I2C_PCA9548_SC6_EMC1053_SCL: R183.2(B) U10.10
I2C_PCA9548_SC6_EMC1412_SCL: R299.2(B) U4.8
I2C_PCA9548_SC6_FRU_SCL: R280.1 U7.6
I2C_PCA9548_SD0_SLOT4_R_SDA: R19.1 U2.4
I2C_PCA9548_SD0_SLOT4_SDA: Q16.D R19.2(B) R95.2(B) R225.1
I2C_PCA9548_SD1_SLOT3_R_SDA: R21.1 U2.6
I2C_PCA9548_SD1_SLOT3_SDA: Q17.D R21.2(B) R97.2(B) R223.1
I2C_PCA9548_SD2_SLOT2_R_SDA: R23.1 U2.8
I2C_PCA9548_SD2_SLOT2_SDA: Q18.D R23.2(B) R99.2(B) R227.1
I2C_PCA9548_SD3_SLOT1_R_SDA: R25.1 U2.10
I2C_PCA9548_SD3_SLOT1_SDA: Q24.D R25.2(B) R101.2(B) R233.1
I2C_PCA9548_SD5_3V3_PE_SDA: CON1.3 Q23.S R209.2(B) R235.2(B) U12.6
I2C_PCA9548_SD5_P1V8_SDA: R278.2(B) U1.R7 U12.3
I2C_PCA9548_SD5_PE_R_SDA: R27.1 U2.15
I2C_PCA9548_SD5_PE_SDA: Q23.D R27.2(B) R103.2(B) R235.1
I2C_PCA9548_SD6_3V3_CLK_R_SDA: R89.2(B) U3.8
I2C_PCA9548_SD6_3V3_CLK_SDA: Q22.S R89.1 R204.2(B) R237.2(B)
I2C_PCA9548_SD6_CLK_R_SDA: R29.1 U2.17
I2C_PCA9548_SD6_CLK_SDA: Q22.D R29.2(B) R105.2(B) R184.1 R237.1 R279.2(B) R300.1
I2C_PCA9548_SD6_EMC1053_SDA: R184.2(B) U10.9
I2C_PCA9548_SD6_EMC1412_SDA: R300.2(B) U4.7
I2C_PCA9548_SD6_FRU_SDA: R279.1 U7.5
I2C_PE_SCL: J5.B5 R86.1
I2C_PE_SCL_R: R86.2(B) R87.2(B) U2.22
I2C_PE_SDA: J5.B6 R85.1
I2C_PE_SDA_R: R85.2(B) R88.2(B) U2.23
I2C_SLOT1_2N7002_G_SCL: Q21.G R162.2(B)
I2C_SLOT1_2N7002_G_SDA: Q24.G R192.2(B)
I2C_SLOT1_3V3_SCL: J1.B5 Q21.S R203.2(B) R228.2(B)
I2C_SLOT1_3V3_SDA: J1.B6 Q24.S R210.2(B) R233.2(B)
I2C_SLOT2_2N7002_G_SCL: Q15.G R107.2(B)
I2C_SLOT2_2N7002_G_SDA: Q18.G R153.2(B)
I2C_SLOT2_3V3_SCL: J2.B5 Q15.S R156.2(B) R226.2(B)
I2C_SLOT2_3V3_SDA: J2.B6 Q18.S R159.2(B) R227.2(B)
I2C_SLOT3_2N7002_G_SCL: Q14.G R94.2(B)
I2C_SLOT3_2N7002_G_SDA: Q17.G R152.2(B)
I2C_SLOT3_3V3_SCL: J3.B5 Q14.S R155.2(B) R222.2(B)
I2C_SLOT3_3V3_SDA: J3.B6 Q17.S R158.2(B) R223.2(B)
I2C_SLOT4_2N7002_G_SCL: Q13.G R93.2(B)
I2C_SLOT4_2N7002_G_SDA: Q16.G R108.2(B)
I2C_SLOT4_3V3_SCL: J4.B5 Q13.S R154.2(B) R224.2(B)
I2C_SLOT4_3V3_SDA: J4.B6 Q16.S R157.2(B) R225.2(B)
NC_CLK_100M_5_DN: U3.37
NC_CLK_100M_5_DP: U3.36
NC_CLK_BUF_DFBOUT_DN: U3.10
NC_CLK_BUF_DFBOUT_DP: U3.11
NC_CLK_BUF_NC: U3.30
NC_CLK_BUF_NC_1: U3.40
NC_P0V9_1P3: PU15.3
NC_P0V9_2P3: PU13.3
NC_P0V9_COMP2: PU21.15
NC_P0V9_DLY2: PU21.9
NC_P0V9_FB2: PU21.16
NC_P0V9_ILIMT2: PU21.13
NC_P0V9_OTP2: PU21.14
NC_P0V9_PG2: PU21.6
NC_P0V9_THWN1: PU15.38
NC_P0V9A_VP: PU23.16
NC_P1V8_P5: PU18.5
NC_P3V3_VP: PU17.16
NC_PEX8796_A2: U1.A2
NC_PEX8796_A30: U1.A30
NC_PEX8796_A33: U1.A33
NC_PEX8796_AA6: U1.AA6
NC_PEX8796_AB1: U1.AB1
NC_PEX8796_AB2: U1.AB2
NC_PEX8796_AB4: U1.AB4
NC_PEX8796_AB5: U1.AB5
NC_PEX8796_AC6: U1.AC6
NC_PEX8796_AC27: U1.AC27
NC_PEX8796_AD29: U1.AD29
NC_PEX8796_AF14: U1.AF14
NC_PEX8796_AF17: U1.AF17
NC_PEX8796_AF20: U1.AF20
NC_PEX8796_AG26: U1.AG26
NC_PEX8796_AH26: U1.AH26
NC_PEX8796_AJ14: U1.AJ14
NC_PEX8796_AL32: U1.AL32
NC_PEX8796_AM32: U1.AM32
NC_PEX8796_B32: U1.B32
NC_PEX8796_D2: U1.D2
NC_PEX8796_F17: U1.F17
NC_PEX8796_G19: U1.G19
NC_PEX8796_G20: U1.G20
NC_PEX8796_J16: U1.J16
NC_PEX8796_J25: U1.J25
NC_PEX8796_K20: U1.K20
NC_PEX8796_K24: U1.K24
NC_PEX8796_K29: U1.K29
NC_PEX8796_M8: U1.M8
NC_PEX8796_N27: U1.N27
NC_PEX8796_N30: U1.N30
NC_PEX8796_N31: U1.N31
NC_PEX8796_N33: U1.N33
NC_PEX8796_N34: U1.N34
NC_PEX8796_P6: U1.P6
NC_PEX8796_P27: U1.P27
NC_PEX8796_P29: U1.P29
NC_PEX8796_R29: U1.R29
NC_PEX8796_T27: U1.T27
NC_PEX8796_U7: U1.U7
NC_PEX8796_U27: U1.U27
NC_PEX8796_W7: U1.W7
NC_PEX8796_Y6: U1.Y6
NC_PEX8796_Y27: U1.Y27
PCA9617_EN: R211.1 R296.2(B) U12.5
PCIE_SLOT1_WAKE_N: J1.B11 R5.2(B)
PCIE_SLOT2_WAKE_N: J2.B11 R6.2(B)
PCIE_SLOT3_WAKE_N: J3.B11 R7.2(B)
PCIE_SLOT4_WAKE_N: J4.B11 R8.2(B)
PCIE_X16_SLOT_PRES_N: J5.A1 J5.B17 J5.B31 J5.B48 J5.B81 R9.1
PD_JTAG_TRST_N: R346.1 U1.P7
PD_SLOT1_B81: J1.B81 R200.2(B)
PD_SLOT2_B81: J2.B81 R199.2(B)
PD_SLOT3_B81: J3.B81 R198.2(B)
PD_SLOT4_B81: J4.B81 R197.2(B)
PD_STRAP_RESERVED_0: R111.2(B) U1.AM4
PD_STRAP_RESERVED_1: R112.2(B) U1.AC8
PD_STRAP_RESERVED_2: R164.2(B) U1.H8
PD_STRAP_RESERVED_3: R165.2(B) U1.AF12
PD_STRAP_RESERVED_4: R166.2(B) U1.M7
PD_STRAP_RESERVED_5: R167.2(B) U1.G9
PD_STRAP_RESERVED_6: R168.2(B) U1.AP5
PD_STRAP_RESERVED_7: R169.2(B) U1.AC9
PD_STRAP_RESERVED_8: R170.2(B) U1.AF19
PD_STRAP_RESERVED_9: R171.2(B) U1.AH18
PD_STRAP_RESERVED_10: R172.2(B) R173.1 U1.AF10
PD_STRAP_RESERVED_11: R174.1 U1.AD7
PD_STRAP_RESERVED_12: R175.1 U1.AN4
PD_STRAP_RESERVED_13: R176.1 U1.V7
PD_STRAP_RESERVED_15: R324.2(B) U1.AC7
PD_STRAP_SNT0_PORTCFG1: R318.1 U1.AF11
PD_STRAP_SNT1_PORTCFG1: R319.1 U1.J10
PD_STRAP_SNT2_PORTCFG1: R320.1 U1.AF23
PD_STRAP_SNT3_PORTCFG1: R321.1 U1.G25
PD_STRAP_SNT4_PORTCFG1: R322.1 U1.N28
PD_STRAP_SNT5_PORTCFG1: R323.1 U1.K26
PD_VOE_N: R76.2(B) U3.13 U3.19 U3.22 U3.28 U3.32
PE_CPU_RX_C_DN<0>: C35.1 U1.V1
PE_CPU_RX_C_DN<1>: C36.1 U1.W1
PE_CPU_RX_C_DN<2>: C37.1 U1.Y1
PE_CPU_RX_C_DN<3>: C38.1 U1.AA1
PE_CPU_RX_C_DN<4>: C91.1 U1.AC1
PE_CPU_RX_C_DN<5>: C92.1 U1.AD1
PE_CPU_RX_C_DN<6>: C93.1 U1.AE1
PE_CPU_RX_C_DN<7>: C94.1 U1.AF1
PE_CPU_RX_C_DN<8>: C95.1 U1.AG1
PE_CPU_RX_C_DN<9>: C96.1 U1.AH1
PE_CPU_RX_C_DN<10>: C97.1 U1.AJ1
PE_CPU_RX_C_DN<11>: C98.1 U1.AK1
PE_CPU_RX_C_DN<12>: C99.1 U1.AP7
PE_CPU_RX_C_DN<13>: C100.1 U1.AP8
PE_CPU_RX_C_DN<14>: C101.1 U1.AP9
PE_CPU_RX_C_DN<15>: C102.1 U1.AP10
PE_CPU_RX_C_DP<0>: C23.1 U1.V2
PE_CPU_RX_C_DP<1>: C24.1 U1.W2
PE_CPU_RX_C_DP<2>: C25.1 U1.Y2
PE_CPU_RX_C_DP<3>: C26.1 U1.AA2
PE_CPU_RX_C_DP<4>: C79.1 U1.AC2
PE_CPU_RX_C_DP<5>: C80.1 U1.AD2
PE_CPU_RX_C_DP<6>: C81.1 U1.AE2
PE_CPU_RX_C_DP<7>: C82.1 U1.AF2
PE_CPU_RX_C_DP<8>: C83.1 U1.AG2
PE_CPU_RX_C_DP<9>: C84.1 U1.AH2
PE_CPU_RX_C_DP<10>: C85.1 U1.AJ2
PE_CPU_RX_C_DP<11>: C86.1 U1.AK2
PE_CPU_RX_C_DP<12>: C87.1 U1.AN7
PE_CPU_RX_C_DP<13>: C88.1 U1.AN8
PE_CPU_RX_C_DP<14>: C89.1 U1.AN9
PE_CPU_RX_C_DP<15>: C90.1 U1.AN10
PE_CPU_RX_DN<0>: C35.2(B) J5.A17
PE_CPU_RX_DN<1>: C36.2(B) J5.A22
PE_CPU_RX_DN<2>: C37.2(B) J5.A26
PE_CPU_RX_DN<3>: C38.2(B) J5.A30
PE_CPU_RX_DN<4>: C91.2(B) J5.A36
PE_CPU_RX_DN<5>: C92.2(B) J5.A40
PE_CPU_RX_DN<6>: C93.2(B) J5.A44
PE_CPU_RX_DN<7>: C94.2(B) J5.A48
PE_CPU_RX_DN<8>: C95.2(B) J5.A53
PE_CPU_RX_DN<9>: C96.2(B) J5.A57
PE_CPU_RX_DN<10>: C97.2(B) J5.A61
PE_CPU_RX_DN<11>: C98.2(B) J5.A65
PE_CPU_RX_DN<12>: C99.2(B) J5.A69
PE_CPU_RX_DN<13>: C100.2(B) J5.A73
PE_CPU_RX_DN<14>: C101.2(B) J5.A77
PE_CPU_RX_DN<15>: C102.2(B) J5.A81
PE_CPU_RX_DP<0>: C23.2(B) J5.A16
PE_CPU_RX_DP<1>: C24.2(B) J5.A21
PE_CPU_RX_DP<2>: C25.2(B) J5.A25
PE_CPU_RX_DP<3>: C26.2(B) J5.A29
PE_CPU_RX_DP<4>: C79.2(B) J5.A35
PE_CPU_RX_DP<5>: C80.2(B) J5.A39
PE_CPU_RX_DP<6>: C81.2(B) J5.A43
PE_CPU_RX_DP<7>: C82.2(B) J5.A47
PE_CPU_RX_DP<8>: C83.2(B) J5.A52
PE_CPU_RX_DP<9>: C84.2(B) J5.A56
PE_CPU_RX_DP<10>: C85.2(B) J5.A60
PE_CPU_RX_DP<11>: C86.2(B) J5.A64
PE_CPU_RX_DP<12>: C87.2(B) J5.A68
PE_CPU_RX_DP<13>: C88.2(B) J5.A72
PE_CPU_RX_DP<14>: C89.2(B) J5.A76
PE_CPU_RX_DP<15>: C90.2(B) J5.A80
PE_CPU_TX_DN<0>: J5.B15 U1.V4
PE_CPU_TX_DN<1>: J5.B20 U1.W4
PE_CPU_TX_DN<2>: J5.B24 U1.Y4
PE_CPU_TX_DN<3>: J5.B28 U1.AA4
PE_CPU_TX_DN<4>: J5.B34 U1.AC4
PE_CPU_TX_DN<5>: J5.B38 U1.AD4
PE_CPU_TX_DN<6>: J5.B42 U1.AE4
PE_CPU_TX_DN<7>: J5.B46 U1.AF4
PE_CPU_TX_DN<8>: J5.B51 U1.AG4
PE_CPU_TX_DN<9>: J5.B55 U1.AH4
PE_CPU_TX_DN<10>: J5.B59 U1.AJ4
PE_CPU_TX_DN<11>: J5.B63 U1.AK4
PE_CPU_TX_DN<12>: J5.B67 U1.AL7
PE_CPU_TX_DN<13>: J5.B71 U1.AL8
PE_CPU_TX_DN<14>: J5.B75 U1.AL9
PE_CPU_TX_DN<15>: J5.B79 U1.AL10
PE_CPU_TX_DP<0>: J5.B14 U1.V5
PE_CPU_TX_DP<1>: J5.B19 U1.W5
PE_CPU_TX_DP<2>: J5.B23 U1.Y5
PE_CPU_TX_DP<3>: J5.B27 U1.AA5
PE_CPU_TX_DP<4>: J5.B33 U1.AC5
PE_CPU_TX_DP<5>: J5.B37 U1.AD5
PE_CPU_TX_DP<6>: J5.B41 U1.AE5
PE_CPU_TX_DP<7>: J5.B45 U1.AF5
PE_CPU_TX_DP<8>: J5.B50 U1.AG5
PE_CPU_TX_DP<9>: J5.B54 U1.AH5
PE_CPU_TX_DP<10>: J5.B58 U1.AJ5
PE_CPU_TX_DP<11>: J5.B62 U1.AK5
PE_CPU_TX_DP<12>: J5.B66 U1.AK7
PE_CPU_TX_DP<13>: J5.B70 U1.AK8
PE_CPU_TX_DP<14>: J5.B74 U1.AK9
PE_CPU_TX_DP<15>: J5.B78 U1.AK10
PE_SLOT1_PRES_N: J1.A1 R271.2(B)
PE_SLOT1_RX_DN<0>: J1.A17 U1.D8
PE_SLOT1_RX_DN<1>: J1.A22 U1.D7
PE_SLOT1_RX_DN<2>: J1.A26 U1.D6
PE_SLOT1_RX_DN<3>: J1.A30 U1.D5
PE_SLOT1_RX_DN<4>: J1.A36 U1.F4
PE_SLOT1_RX_DN<5>: J1.A40 U1.G4
PE_SLOT1_RX_DN<6>: J1.A44 U1.H4
PE_SLOT1_RX_DN<7>: J1.A48 U1.J4
PE_SLOT1_RX_DN<8>: J1.A53 U1.K4
PE_SLOT1_RX_DN<9>: J1.A57 U1.L4
PE_SLOT1_RX_DN<10>: J1.A61 U1.M4
PE_SLOT1_RX_DN<11>: J1.A65 U1.N4
PE_SLOT1_RX_DN<12>: J1.A69 U1.P4
PE_SLOT1_RX_DN<13>: J1.A73 U1.R4
PE_SLOT1_RX_DN<14>: J1.A77 U1.T4
PE_SLOT1_RX_DN<15>: J1.A81 U1.U4
PE_SLOT1_RX_DP<0>: J1.A16 U1.E8
PE_SLOT1_RX_DP<1>: J1.A21 U1.E7
PE_SLOT1_RX_DP<2>: J1.A25 U1.E6
PE_SLOT1_RX_DP<3>: J1.A29 U1.E5
PE_SLOT1_RX_DP<4>: J1.A35 U1.F5
PE_SLOT1_RX_DP<5>: J1.A39 U1.G5
PE_SLOT1_RX_DP<6>: J1.A43 U1.H5
PE_SLOT1_RX_DP<7>: J1.A47 U1.J5
PE_SLOT1_RX_DP<8>: J1.A52 U1.K5
PE_SLOT1_RX_DP<9>: J1.A56 U1.L5
PE_SLOT1_RX_DP<10>: J1.A60 U1.M5
PE_SLOT1_RX_DP<11>: J1.A64 U1.N5
PE_SLOT1_RX_DP<12>: J1.A68 U1.P5
PE_SLOT1_RX_DP<13>: J1.A72 U1.R5
PE_SLOT1_RX_DP<14>: J1.A76 U1.T5
PE_SLOT1_RX_DP<15>: J1.A80 U1.U5
PE_SLOT1_TX_C_DN<0>: C199.1 U1.A8
PE_SLOT1_TX_C_DN<1>: C200.1 U1.A7
PE_SLOT1_TX_C_DN<2>: C201.1 U1.A6
PE_SLOT1_TX_C_DN<3>: C202.1 U1.A5
PE_SLOT1_TX_C_DN<4>: C203.1 U1.F1
PE_SLOT1_TX_C_DN<5>: C204.1 U1.G1
PE_SLOT1_TX_C_DN<6>: C205.1 U1.H1
PE_SLOT1_TX_C_DN<7>: C206.1 U1.J1
PE_SLOT1_TX_C_DN<8>: C207.1 U1.K1
PE_SLOT1_TX_C_DN<9>: C208.1 U1.L1
PE_SLOT1_TX_C_DN<10>: C209.1 U1.M1
PE_SLOT1_TX_C_DN<11>: C210.1 U1.N1
PE_SLOT1_TX_C_DN<12>: C211.1 U1.P1
PE_SLOT1_TX_C_DN<13>: C212.1 U1.R1
PE_SLOT1_TX_C_DN<14>: C213.1 U1.T1
PE_SLOT1_TX_C_DN<15>: C214.1 U1.U1
PE_SLOT1_TX_C_DP<0>: C183.1 U1.B8
PE_SLOT1_TX_C_DP<1>: C184.1 U1.B7
PE_SLOT1_TX_C_DP<2>: C185.1 U1.B6
PE_SLOT1_TX_C_DP<3>: C186.1 U1.B5
PE_SLOT1_TX_C_DP<4>: C187.1 U1.F2
PE_SLOT1_TX_C_DP<5>: C188.1 U1.G2
PE_SLOT1_TX_C_DP<6>: C189.1 U1.H2
PE_SLOT1_TX_C_DP<7>: C190.1 U1.J2
PE_SLOT1_TX_C_DP<8>: C191.1 U1.K2
PE_SLOT1_TX_C_DP<9>: C192.1 U1.L2
PE_SLOT1_TX_C_DP<10>: C193.1 U1.M2
PE_SLOT1_TX_C_DP<11>: C194.1 U1.N2
PE_SLOT1_TX_C_DP<12>: C195.1 U1.P2
PE_SLOT1_TX_C_DP<13>: C196.1 U1.R2
PE_SLOT1_TX_C_DP<14>: C197.1 U1.T2
PE_SLOT1_TX_C_DP<15>: C198.1 U1.U2
PE_SLOT1_TX_DN<0>: C199.2(B) J1.B15
PE_SLOT1_TX_DN<1>: C200.2(B) J1.B20
PE_SLOT1_TX_DN<2>: C201.2(B) J1.B24
PE_SLOT1_TX_DN<3>: C202.2(B) J1.B28
PE_SLOT1_TX_DN<4>: C203.2(B) J1.B34
PE_SLOT1_TX_DN<5>: C204.2(B) J1.B38
PE_SLOT1_TX_DN<6>: C205.2(B) J1.B42
PE_SLOT1_TX_DN<7>: C206.2(B) J1.B46
PE_SLOT1_TX_DN<8>: C207.2(B) J1.B51
PE_SLOT1_TX_DN<9>: C208.2(B) J1.B55
PE_SLOT1_TX_DN<10>: C209.2(B) J1.B59
PE_SLOT1_TX_DN<11>: C210.2(B) J1.B63
PE_SLOT1_TX_DN<12>: C211.2(B) J1.B67
PE_SLOT1_TX_DN<13>: C212.2(B) J1.B71
PE_SLOT1_TX_DN<14>: C213.2(B) J1.B75
PE_SLOT1_TX_DN<15>: C214.2(B) J1.B79
PE_SLOT1_TX_DP<0>: C183.2(B) J1.B14
PE_SLOT1_TX_DP<1>: C184.2(B) J1.B19
PE_SLOT1_TX_DP<2>: C185.2(B) J1.B23
PE_SLOT1_TX_DP<3>: C186.2(B) J1.B27
PE_SLOT1_TX_DP<4>: C187.2(B) J1.B33
PE_SLOT1_TX_DP<5>: C188.2(B) J1.B37
PE_SLOT1_TX_DP<6>: C189.2(B) J1.B41
PE_SLOT1_TX_DP<7>: C190.2(B) J1.B45
PE_SLOT1_TX_DP<8>: C191.2(B) J1.B50
PE_SLOT1_TX_DP<9>: C192.2(B) J1.B54
PE_SLOT1_TX_DP<10>: C193.2(B) J1.B58
PE_SLOT1_TX_DP<11>: C194.2(B) J1.B62
PE_SLOT1_TX_DP<12>: C195.2(B) J1.B66
PE_SLOT1_TX_DP<13>: C196.2(B) J1.B70
PE_SLOT1_TX_DP<14>: C197.2(B) J1.B74
PE_SLOT1_TX_DP<15>: C198.2(B) J1.B78
PE_SLOT2_PRES_N: J2.A1 R270.2(B)
PE_SLOT2_RX_DN<0>: J2.A17 U1.D24
PE_SLOT2_RX_DN<1>: J2.A22 U1.D23
PE_SLOT2_RX_DN<2>: J2.A26 U1.D22
PE_SLOT2_RX_DN<3>: J2.A30 U1.D21
PE_SLOT2_RX_DN<4>: J2.A36 U1.D20
PE_SLOT2_RX_DN<5>: J2.A40 U1.D19
PE_SLOT2_RX_DN<6>: J2.A44 U1.D18
PE_SLOT2_RX_DN<7>: J2.A48 U1.D17
PE_SLOT2_RX_DN<8>: J2.A53 U1.D16
PE_SLOT2_RX_DN<9>: J2.A57 U1.D15
PE_SLOT2_RX_DN<10>: J2.A61 U1.D14
PE_SLOT2_RX_DN<11>: J2.A65 U1.D13
PE_SLOT2_RX_DN<12>: J2.A69 U1.D12
PE_SLOT2_RX_DN<13>: J2.A73 U1.D11
PE_SLOT2_RX_DN<14>: J2.A77 U1.D10
PE_SLOT2_RX_DN<15>: J2.A81 U1.D9
PE_SLOT2_RX_DP<0>: J2.A16 U1.E24
PE_SLOT2_RX_DP<1>: J2.A21 U1.E23
PE_SLOT2_RX_DP<2>: J2.A25 U1.E22
PE_SLOT2_RX_DP<3>: J2.A29 U1.E21
PE_SLOT2_RX_DP<4>: J2.A35 U1.E20
PE_SLOT2_RX_DP<5>: J2.A39 U1.E19
PE_SLOT2_RX_DP<6>: J2.A43 U1.E18
PE_SLOT2_RX_DP<7>: J2.A47 U1.E17
PE_SLOT2_RX_DP<8>: J2.A52 U1.E16
PE_SLOT2_RX_DP<9>: J2.A56 U1.E15
PE_SLOT2_RX_DP<10>: J2.A60 U1.E14
PE_SLOT2_RX_DP<11>: J2.A64 U1.E13
PE_SLOT2_RX_DP<12>: J2.A68 U1.E12
PE_SLOT2_RX_DP<13>: J2.A72 U1.E11
PE_SLOT2_RX_DP<14>: J2.A76 U1.E10
PE_SLOT2_RX_DP<15>: J2.A80 U1.E9
PE_SLOT2_TX_C_DN<0>: C31.1 U1.A24
PE_SLOT2_TX_C_DN<1>: C32.1 U1.A23
PE_SLOT2_TX_C_DN<2>: C33.1 U1.A22
PE_SLOT2_TX_C_DN<3>: C34.1 U1.A21
PE_SLOT2_TX_C_DN<4>: C67.1 U1.A20
PE_SLOT2_TX_C_DN<5>: C68.1 U1.A19
PE_SLOT2_TX_C_DN<6>: C69.1 U1.A18
PE_SLOT2_TX_C_DN<7>: C70.1 U1.A17
PE_SLOT2_TX_C_DN<8>: C71.1 U1.A16
PE_SLOT2_TX_C_DN<9>: C72.1 U1.A15
PE_SLOT2_TX_C_DN<10>: C73.1 U1.A14
PE_SLOT2_TX_C_DN<11>: C74.1 U1.A13
PE_SLOT2_TX_C_DN<12>: C75.1 U1.A12
PE_SLOT2_TX_C_DN<13>: C76.1 U1.A11
PE_SLOT2_TX_C_DN<14>: C77.1 U1.A10
PE_SLOT2_TX_C_DN<15>: C78.1 U1.A9
PE_SLOT2_TX_C_DP<0>: C27.1 U1.B24
PE_SLOT2_TX_C_DP<1>: C28.1 U1.B23
PE_SLOT2_TX_C_DP<2>: C29.1 U1.B22
PE_SLOT2_TX_C_DP<3>: C30.1 U1.B21
PE_SLOT2_TX_C_DP<4>: C55.1 U1.B20
PE_SLOT2_TX_C_DP<5>: C56.1 U1.B19
PE_SLOT2_TX_C_DP<6>: C57.1 U1.B18
PE_SLOT2_TX_C_DP<7>: C58.1 U1.B17
PE_SLOT2_TX_C_DP<8>: C59.1 U1.B16
PE_SLOT2_TX_C_DP<9>: C60.1 U1.B15
PE_SLOT2_TX_C_DP<10>: C61.1 U1.B14
PE_SLOT2_TX_C_DP<11>: C62.1 U1.B13
PE_SLOT2_TX_C_DP<12>: C63.1 U1.B12
PE_SLOT2_TX_C_DP<13>: C64.1 U1.B11
PE_SLOT2_TX_C_DP<14>: C65.1 U1.B10
PE_SLOT2_TX_C_DP<15>: C66.1 U1.B9
PE_SLOT2_TX_DN<0>: C31.2(B) J2.B15
PE_SLOT2_TX_DN<1>: C32.2(B) J2.B20
PE_SLOT2_TX_DN<2>: C33.2(B) J2.B24
PE_SLOT2_TX_DN<3>: C34.2(B) J2.B28
PE_SLOT2_TX_DN<4>: C67.2(B) J2.B34
PE_SLOT2_TX_DN<5>: C68.2(B) J2.B38
PE_SLOT2_TX_DN<6>: C69.2(B) J2.B42
PE_SLOT2_TX_DN<7>: C70.2(B) J2.B46
PE_SLOT2_TX_DN<8>: C71.2(B) J2.B51
PE_SLOT2_TX_DN<9>: C72.2(B) J2.B55
PE_SLOT2_TX_DN<10>: C73.2(B) J2.B59
PE_SLOT2_TX_DN<11>: C74.2(B) J2.B63
PE_SLOT2_TX_DN<12>: C75.2(B) J2.B67
PE_SLOT2_TX_DN<13>: C76.2(B) J2.B71
PE_SLOT2_TX_DN<14>: C77.2(B) J2.B75
PE_SLOT2_TX_DN<15>: C78.2(B) J2.B79
PE_SLOT2_TX_DP<0>: C27.2(B) J2.B14
PE_SLOT2_TX_DP<1>: C28.2(B) J2.B19
PE_SLOT2_TX_DP<2>: C29.2(B) J2.B23
PE_SLOT2_TX_DP<3>: C30.2(B) J2.B27
PE_SLOT2_TX_DP<4>: C55.2(B) J2.B33
PE_SLOT2_TX_DP<5>: C56.2(B) J2.B37
PE_SLOT2_TX_DP<6>: C57.2(B) J2.B41
PE_SLOT2_TX_DP<7>: C58.2(B) J2.B45
PE_SLOT2_TX_DP<8>: C59.2(B) J2.B50
PE_SLOT2_TX_DP<9>: C60.2(B) J2.B54
PE_SLOT2_TX_DP<10>: C61.2(B) J2.B58
PE_SLOT2_TX_DP<11>: C62.2(B) J2.B62
PE_SLOT2_TX_DP<12>: C63.2(B) J2.B66
PE_SLOT2_TX_DP<13>: C64.2(B) J2.B70
PE_SLOT2_TX_DP<14>: C65.2(B) J2.B74
PE_SLOT2_TX_DP<15>: C66.2(B) J2.B78
PE_SLOT3_PRES_N: J3.A1 R269.2(B)
PE_SLOT3_RX_DN<0>: J3.A17 U1.U31
PE_SLOT3_RX_DN<1>: J3.A22 U1.T31
PE_SLOT3_RX_DN<2>: J3.A26 U1.R31
PE_SLOT3_RX_DN<3>: J3.A30 U1.P31
PE_SLOT3_RX_DN<4>: J3.A36 U1.M31
PE_SLOT3_RX_DN<5>: J3.A40 U1.L31
PE_SLOT3_RX_DN<6>: J3.A44 U1.K31
PE_SLOT3_RX_DN<7>: J3.A48 U1.J31
PE_SLOT3_RX_DN<8>: J3.A53 U1.H31
PE_SLOT3_RX_DN<9>: J3.A57 U1.G31
PE_SLOT3_RX_DN<10>: J3.A61 U1.F31
PE_SLOT3_RX_DN<11>: J3.A65 U1.E31
PE_SLOT3_RX_DN<12>: J3.A69 U1.D28
PE_SLOT3_RX_DN<13>: J3.A73 U1.D27
PE_SLOT3_RX_DN<14>: J3.A77 U1.D26
PE_SLOT3_RX_DN<15>: J3.A81 U1.D25
PE_SLOT3_RX_DP<0>: J3.A16 U1.U30
PE_SLOT3_RX_DP<1>: J3.A21 U1.T30
PE_SLOT3_RX_DP<2>: J3.A25 U1.R30
PE_SLOT3_RX_DP<3>: J3.A29 U1.P30
PE_SLOT3_RX_DP<4>: J3.A35 U1.M30
PE_SLOT3_RX_DP<5>: J3.A39 U1.L30
PE_SLOT3_RX_DP<6>: J3.A43 U1.K30
PE_SLOT3_RX_DP<7>: J3.A47 U1.J30
PE_SLOT3_RX_DP<8>: J3.A52 U1.H30
PE_SLOT3_RX_DP<9>: J3.A56 U1.G30
PE_SLOT3_RX_DP<10>: J3.A60 U1.F30
PE_SLOT3_RX_DP<11>: J3.A64 U1.E30
PE_SLOT3_RX_DP<12>: J3.A68 U1.E28
PE_SLOT3_RX_DP<13>: J3.A72 U1.E27
PE_SLOT3_RX_DP<14>: J3.A76 U1.E26
PE_SLOT3_RX_DP<15>: J3.A80 U1.E25
PE_SLOT3_TX_C_DN<0>: C43.1 U1.U34
PE_SLOT3_TX_C_DN<1>: C44.1 U1.T34
PE_SLOT3_TX_C_DN<2>: C45.1 U1.R34
PE_SLOT3_TX_C_DN<3>: C46.1 U1.P34
PE_SLOT3_TX_C_DN<4>: C115.1 U1.M34
PE_SLOT3_TX_C_DN<5>: C116.1 U1.L34
PE_SLOT3_TX_C_DN<6>: C117.1 U1.K34
PE_SLOT3_TX_C_DN<7>: C118.1 U1.J34
PE_SLOT3_TX_C_DN<8>: C119.1 U1.H34
PE_SLOT3_TX_C_DN<9>: C120.1 U1.G34
PE_SLOT3_TX_C_DN<10>: C121.1 U1.F34
PE_SLOT3_TX_C_DN<11>: C122.1 U1.E34
PE_SLOT3_TX_C_DN<12>: C123.1 U1.A28
PE_SLOT3_TX_C_DN<13>: C124.1 U1.A27
PE_SLOT3_TX_C_DN<14>: C125.1 U1.A26
PE_SLOT3_TX_C_DN<15>: C126.1 U1.A25
PE_SLOT3_TX_C_DP<0>: C39.1 U1.U33
PE_SLOT3_TX_C_DP<1>: C40.1 U1.T33
PE_SLOT3_TX_C_DP<2>: C41.1 U1.R33
PE_SLOT3_TX_C_DP<3>: C42.1 U1.P33
PE_SLOT3_TX_C_DP<4>: C103.1 U1.M33
PE_SLOT3_TX_C_DP<5>: C104.1 U1.L33
PE_SLOT3_TX_C_DP<6>: C105.1 U1.K33
PE_SLOT3_TX_C_DP<7>: C106.1 U1.J33
PE_SLOT3_TX_C_DP<8>: C107.1 U1.H33
PE_SLOT3_TX_C_DP<9>: C108.1 U1.G33
PE_SLOT3_TX_C_DP<10>: C109.1 U1.F33
PE_SLOT3_TX_C_DP<11>: C110.1 U1.E33
PE_SLOT3_TX_C_DP<12>: C111.1 U1.B28
PE_SLOT3_TX_C_DP<13>: C112.1 U1.B27
PE_SLOT3_TX_C_DP<14>: C113.1 U1.B26
PE_SLOT3_TX_C_DP<15>: C114.1 U1.B25
PE_SLOT3_TX_DN<0>: C43.2(B) J3.B15
PE_SLOT3_TX_DN<1>: C44.2(B) J3.B20
PE_SLOT3_TX_DN<2>: C45.2(B) J3.B24
PE_SLOT3_TX_DN<3>: C46.2(B) J3.B28
PE_SLOT3_TX_DN<4>: C115.2(B) J3.B34
PE_SLOT3_TX_DN<5>: C116.2(B) J3.B38
PE_SLOT3_TX_DN<6>: C117.2(B) J3.B42
PE_SLOT3_TX_DN<7>: C118.2(B) J3.B46
PE_SLOT3_TX_DN<8>: C119.2(B) J3.B51
PE_SLOT3_TX_DN<9>: C120.2(B) J3.B55
PE_SLOT3_TX_DN<10>: C121.2(B) J3.B59
PE_SLOT3_TX_DN<11>: C122.2(B) J3.B63
PE_SLOT3_TX_DN<12>: C123.2(B) J3.B67
PE_SLOT3_TX_DN<13>: C124.2(B) J3.B71
PE_SLOT3_TX_DN<14>: C125.2(B) J3.B75
PE_SLOT3_TX_DN<15>: C126.2(B) J3.B79
PE_SLOT3_TX_DP<0>: C39.2(B) J3.B14
PE_SLOT3_TX_DP<1>: C40.2(B) J3.B19
PE_SLOT3_TX_DP<2>: C41.2(B) J3.B23
PE_SLOT3_TX_DP<3>: C42.2(B) J3.B27
PE_SLOT3_TX_DP<4>: C103.2(B) J3.B33
PE_SLOT3_TX_DP<5>: C104.2(B) J3.B37
PE_SLOT3_TX_DP<6>: C105.2(B) J3.B41
PE_SLOT3_TX_DP<7>: C106.2(B) J3.B45
PE_SLOT3_TX_DP<8>: C107.2(B) J3.B50
PE_SLOT3_TX_DP<9>: C108.2(B) J3.B54
PE_SLOT3_TX_DP<10>: C109.2(B) J3.B58
PE_SLOT3_TX_DP<11>: C110.2(B) J3.B62
PE_SLOT3_TX_DP<12>: C111.2(B) J3.B66
PE_SLOT3_TX_DP<13>: C112.2(B) J3.B70
PE_SLOT3_TX_DP<14>: C113.2(B) J3.B74
PE_SLOT3_TX_DP<15>: C114.2(B) J3.B78
PE_SLOT4_PRES_N: J4.A1 R115.2(B)
PE_SLOT4_RX_DN<0>: J4.A17 U1.AL27
PE_SLOT4_RX_DN<1>: J4.A22 U1.AL28
PE_SLOT4_RX_DN<2>: J4.A26 U1.AL29
PE_SLOT4_RX_DN<3>: J4.A30 U1.AL30
PE_SLOT4_RX_DN<4>: J4.A36 U1.AJ31
PE_SLOT4_RX_DN<5>: J4.A40 U1.AH31
PE_SLOT4_RX_DN<6>: J4.A44 U1.AG31
PE_SLOT4_RX_DN<7>: J4.A48 U1.AF31
PE_SLOT4_RX_DN<8>: J4.A53 U1.AE31
PE_SLOT4_RX_DN<9>: J4.A57 U1.AD31
PE_SLOT4_RX_DN<10>: J4.A61 U1.AC31
PE_SLOT4_RX_DN<11>: J4.A65 U1.AB31
PE_SLOT4_RX_DN<12>: J4.A69 U1.AA31
PE_SLOT4_RX_DN<13>: J4.A73 U1.Y31
PE_SLOT4_RX_DN<14>: J4.A77 U1.W31
PE_SLOT4_RX_DN<15>: J4.A81 U1.V31
PE_SLOT4_RX_DP<0>: J4.A16 U1.AK27
PE_SLOT4_RX_DP<1>: J4.A21 U1.AK28
PE_SLOT4_RX_DP<2>: J4.A25 U1.AK29
PE_SLOT4_RX_DP<3>: J4.A29 U1.AK30
PE_SLOT4_RX_DP<4>: J4.A35 U1.AJ30
PE_SLOT4_RX_DP<5>: J4.A39 U1.AH30
PE_SLOT4_RX_DP<6>: J4.A43 U1.AG30
PE_SLOT4_RX_DP<7>: J4.A47 U1.AF30
PE_SLOT4_RX_DP<8>: J4.A52 U1.AE30
PE_SLOT4_RX_DP<9>: J4.A56 U1.AD30
PE_SLOT4_RX_DP<10>: J4.A60 U1.AC30
PE_SLOT4_RX_DP<11>: J4.A64 U1.AB30
PE_SLOT4_RX_DP<12>: J4.A68 U1.AA30
PE_SLOT4_RX_DP<13>: J4.A72 U1.Y30
PE_SLOT4_RX_DP<14>: J4.A76 U1.W30
PE_SLOT4_RX_DP<15>: J4.A80 U1.V30
PE_SLOT4_TX_C_DN<0>: C51.1 U1.AP27
PE_SLOT4_TX_C_DN<1>: C52.1 U1.AP28
PE_SLOT4_TX_C_DN<2>: C53.1 U1.AP29
PE_SLOT4_TX_C_DN<3>: C54.1 U1.AP30
PE_SLOT4_TX_C_DN<4>: C139.1 U1.AJ34
PE_SLOT4_TX_C_DN<5>: C140.1 U1.AH34
PE_SLOT4_TX_C_DN<6>: C141.1 U1.AG34
PE_SLOT4_TX_C_DN<7>: C142.1 U1.AF34
PE_SLOT4_TX_C_DN<8>: C143.1 U1.AE34
PE_SLOT4_TX_C_DN<9>: C144.1 U1.AD34
PE_SLOT4_TX_C_DN<10>: C145.1 U1.AC34
PE_SLOT4_TX_C_DN<11>: C146.1 U1.AB34
PE_SLOT4_TX_C_DN<12>: C147.1 U1.AA34
PE_SLOT4_TX_C_DN<13>: C148.1 U1.Y34
PE_SLOT4_TX_C_DN<14>: C149.1 U1.W34
PE_SLOT4_TX_C_DN<15>: C150.1 U1.V34
PE_SLOT4_TX_C_DP<0>: C47.1 U1.AN27
PE_SLOT4_TX_C_DP<1>: C48.1 U1.AN28
PE_SLOT4_TX_C_DP<2>: C49.1 U1.AN29
PE_SLOT4_TX_C_DP<3>: C50.1 U1.AN30
PE_SLOT4_TX_C_DP<4>: C127.1 U1.AJ33
PE_SLOT4_TX_C_DP<5>: C128.1 U1.AH33
PE_SLOT4_TX_C_DP<6>: C129.1 U1.AG33
PE_SLOT4_TX_C_DP<7>: C130.1 U1.AF33
PE_SLOT4_TX_C_DP<8>: C131.1 U1.AE33
PE_SLOT4_TX_C_DP<9>: C132.1 U1.AD33
PE_SLOT4_TX_C_DP<10>: C133.1 U1.AC33
PE_SLOT4_TX_C_DP<11>: C134.1 U1.AB33
PE_SLOT4_TX_C_DP<12>: C135.1 U1.AA33
PE_SLOT4_TX_C_DP<13>: C136.1 U1.Y33
PE_SLOT4_TX_C_DP<14>: C137.1 U1.W33
PE_SLOT4_TX_C_DP<15>: C138.1 U1.V33
PE_SLOT4_TX_DN<0>: C51.2(B) J4.B15
PE_SLOT4_TX_DN<1>: C52.2(B) J4.B20
PE_SLOT4_TX_DN<2>: C53.2(B) J4.B24
PE_SLOT4_TX_DN<3>: C54.2(B) J4.B28
PE_SLOT4_TX_DN<4>: C139.2(B) J4.B34
PE_SLOT4_TX_DN<5>: C140.2(B) J4.B38
PE_SLOT4_TX_DN<6>: C141.2(B) J4.B42
PE_SLOT4_TX_DN<7>: C142.2(B) J4.B46
PE_SLOT4_TX_DN<8>: C143.2(B) J4.B51
PE_SLOT4_TX_DN<9>: C144.2(B) J4.B55
PE_SLOT4_TX_DN<10>: C145.2(B) J4.B59
PE_SLOT4_TX_DN<11>: C146.2(B) J4.B63
PE_SLOT4_TX_DN<12>: C147.2(B) J4.B67
PE_SLOT4_TX_DN<13>: C148.2(B) J4.B71
PE_SLOT4_TX_DN<14>: C149.2(B) J4.B75
PE_SLOT4_TX_DN<15>: C150.2(B) J4.B79
PE_SLOT4_TX_DP<0>: C47.2(B) J4.B14
PE_SLOT4_TX_DP<1>: C48.2(B) J4.B19
PE_SLOT4_TX_DP<2>: C49.2(B) J4.B23
PE_SLOT4_TX_DP<3>: C50.2(B) J4.B27
PE_SLOT4_TX_DP<4>: C127.2(B) J4.B33
PE_SLOT4_TX_DP<5>: C128.2(B) J4.B37
PE_SLOT4_TX_DP<6>: C129.2(B) J4.B41
PE_SLOT4_TX_DP<7>: C130.2(B) J4.B45
PE_SLOT4_TX_DP<8>: C131.2(B) J4.B50
PE_SLOT4_TX_DP<9>: C132.2(B) J4.B54
PE_SLOT4_TX_DP<10>: C133.2(B) J4.B58
PE_SLOT4_TX_DP<11>: C134.2(B) J4.B62
PE_SLOT4_TX_DP<12>: C135.2(B) J4.B66
PE_SLOT4_TX_DP<13>: C136.2(B) J4.B70
PE_SLOT4_TX_DP<14>: C137.2(B) J4.B74
PE_SLOT4_TX_DP<15>: C138.2(B) J4.B78
PE_SLV_RX_DN<0>: J7.48 U1.AL11
PE_SLV_RX_DN<1>: J7.45 U1.AL12
PE_SLV_RX_DN<2>: J7.42 U1.AL13
PE_SLV_RX_DN<3>: J7.39 U1.AL14
PE_SLV_RX_DN<4>: J7.36 U1.AL15
PE_SLV_RX_DN<5>: J7.33 U1.AL16
PE_SLV_RX_DN<6>: J7.30 U1.AL17
PE_SLV_RX_DN<7>: J7.27 U1.AL18
PE_SLV_RX_DN<8>: J8.72 U1.AL19
PE_SLV_RX_DN<9>: J8.69 U1.AL20
PE_SLV_RX_DN<10>: J8.66 U1.AL21
PE_SLV_RX_DN<11>: J8.63 U1.AL22
PE_SLV_RX_DN<12>: J8.60 U1.AL23
PE_SLV_RX_DN<13>: J8.57 U1.AL24
PE_SLV_RX_DN<14>: J8.54 U1.AL25
PE_SLV_RX_DN<15>: J8.51 U1.AL26
PE_SLV_RX_DP<0>: J7.49 U1.AK11
PE_SLV_RX_DP<1>: J7.46 U1.AK12
PE_SLV_RX_DP<2>: J7.43 U1.AK13
PE_SLV_RX_DP<3>: J7.40 U1.AK14
PE_SLV_RX_DP<4>: J7.37 U1.AK15
PE_SLV_RX_DP<5>: J7.34 U1.AK16
PE_SLV_RX_DP<6>: J7.31 U1.AK17
PE_SLV_RX_DP<7>: J7.28 U1.AK18
PE_SLV_RX_DP<8>: J8.73 U1.AK19
PE_SLV_RX_DP<9>: J8.70 U1.AK20
PE_SLV_RX_DP<10>: J8.67 U1.AK21
PE_SLV_RX_DP<11>: J8.64 U1.AK22
PE_SLV_RX_DP<12>: J8.61 U1.AK23
PE_SLV_RX_DP<13>: J8.58 U1.AK24
PE_SLV_RX_DP<14>: J8.55 U1.AK25
PE_SLV_RX_DP<15>: J8.52 U1.AK26
PE_SLV_TX_C_DN<0>: C167.1 U1.AP11
PE_SLV_TX_C_DN<1>: C168.1 U1.AP12
PE_SLV_TX_C_DN<2>: C169.1 U1.AP13
PE_SLV_TX_C_DN<3>: C170.1 U1.AP14
PE_SLV_TX_C_DN<4>: C171.1 U1.AP15
PE_SLV_TX_C_DN<5>: C172.1 U1.AP16
PE_SLV_TX_C_DN<6>: C173.1 U1.AP17
PE_SLV_TX_C_DN<7>: C174.1 U1.AP18
PE_SLV_TX_C_DN<8>: C175.1 U1.AP19
PE_SLV_TX_C_DN<9>: C176.1 U1.AP20
PE_SLV_TX_C_DN<10>: C177.1 U1.AP21
PE_SLV_TX_C_DN<11>: C178.1 U1.AP22
PE_SLV_TX_C_DN<12>: C179.1 U1.AP23
PE_SLV_TX_C_DN<13>: C180.1 U1.AP24
PE_SLV_TX_C_DN<14>: C181.1 U1.AP25
PE_SLV_TX_C_DN<15>: C182.1 U1.AP26
PE_SLV_TX_C_DP<0>: C151.1 U1.AN11
PE_SLV_TX_C_DP<1>: C152.1 U1.AN12
PE_SLV_TX_C_DP<2>: C153.1 U1.AN13
PE_SLV_TX_C_DP<3>: C154.1 U1.AN14
PE_SLV_TX_C_DP<4>: C155.1 U1.AN15
PE_SLV_TX_C_DP<5>: C156.1 U1.AN16
PE_SLV_TX_C_DP<6>: C157.1 U1.AN17
PE_SLV_TX_C_DP<7>: C158.1 U1.AN18
PE_SLV_TX_C_DP<8>: C159.1 U1.AN19
PE_SLV_TX_C_DP<9>: C160.1 U1.AN20
PE_SLV_TX_C_DP<10>: C161.1 U1.AN21
PE_SLV_TX_C_DP<11>: C162.1 U1.AN22
PE_SLV_TX_C_DP<12>: C163.1 U1.AN23
PE_SLV_TX_C_DP<13>: C164.1 U1.AN24
PE_SLV_TX_C_DP<14>: C165.1 U1.AN25
PE_SLV_TX_C_DP<15>: C166.1 U1.AN26
PE_SLV_TX_DN<0>: C167.2(B) J7.3
PE_SLV_TX_DN<1>: C168.2(B) J7.6
PE_SLV_TX_DN<2>: C169.2(B) J7.9
PE_SLV_TX_DN<3>: C170.2(B) J7.12
PE_SLV_TX_DN<4>: C171.2(B) J7.15
PE_SLV_TX_DN<5>: C172.2(B) J7.18
PE_SLV_TX_DN<6>: C173.2(B) J7.21
PE_SLV_TX_DN<7>: C174.2(B) J7.24
PE_SLV_TX_DN<8>: C175.2(B) J8.3
PE_SLV_TX_DN<9>: C176.2(B) J8.6
PE_SLV_TX_DN<10>: C177.2(B) J8.9
PE_SLV_TX_DN<11>: C178.2(B) J8.12
PE_SLV_TX_DN<12>: C179.2(B) J8.15
PE_SLV_TX_DN<13>: C180.2(B) J8.18
PE_SLV_TX_DN<14>: C181.2(B) J8.21
PE_SLV_TX_DN<15>: C182.2(B) J8.24
PE_SLV_TX_DP<0>: C151.2(B) J7.2
PE_SLV_TX_DP<1>: C152.2(B) J7.5
PE_SLV_TX_DP<2>: C153.2(B) J7.8
PE_SLV_TX_DP<3>: C154.2(B) J7.11
PE_SLV_TX_DP<4>: C155.2(B) J7.14
PE_SLV_TX_DP<5>: C156.2(B) J7.17
PE_SLV_TX_DP<6>: C157.2(B) J7.20
PE_SLV_TX_DP<7>: C158.2(B) J7.23
PE_SLV_TX_DP<8>: C159.2(B) J8.2
PE_SLV_TX_DP<9>: C160.2(B) J8.5
PE_SLV_TX_DP<10>: C161.2(B) J8.8
PE_SLV_TX_DP<11>: C162.2(B) J8.11
PE_SLV_TX_DP<12>: C163.2(B) J8.14
PE_SLV_TX_DP<13>: C164.2(B) J8.17
PE_SLV_TX_DP<14>: C165.2(B) J8.20
PE_SLV_TX_DP<15>: C166.2(B) J8.23
PE_WAKE_N: J5.B11 R5.1 R6.1 R7.1 R8.1
PEX8796_GPIO0: R115.1 R190.2(B) U1.AH14
PEX8796_GPIO1: R189.2(B) R269.1 U1.AF8
PEX8796_GPIO2: R188.2(B) R270.1 U1.AE11
PEX8796_GPIO3: R187.2(B) R271.1 U1.AG12
PEX_EEP_CS_N: R113.1 U1.AG14
PEX_EEP_CS_R_N: R113.2(B) R272.2(B) U6.1
PEX_EEP_HOLD_N: R143.2(B) U6.7
PEX_EEP_SCLK: R116.2(B) U1.AM5
PEX_EEP_SCLK_R: R116.1 U6.6
PEX_EEP_SI: R117.2(B) U1.J11
PEX_EEP_SI_R: R117.1 U6.5
